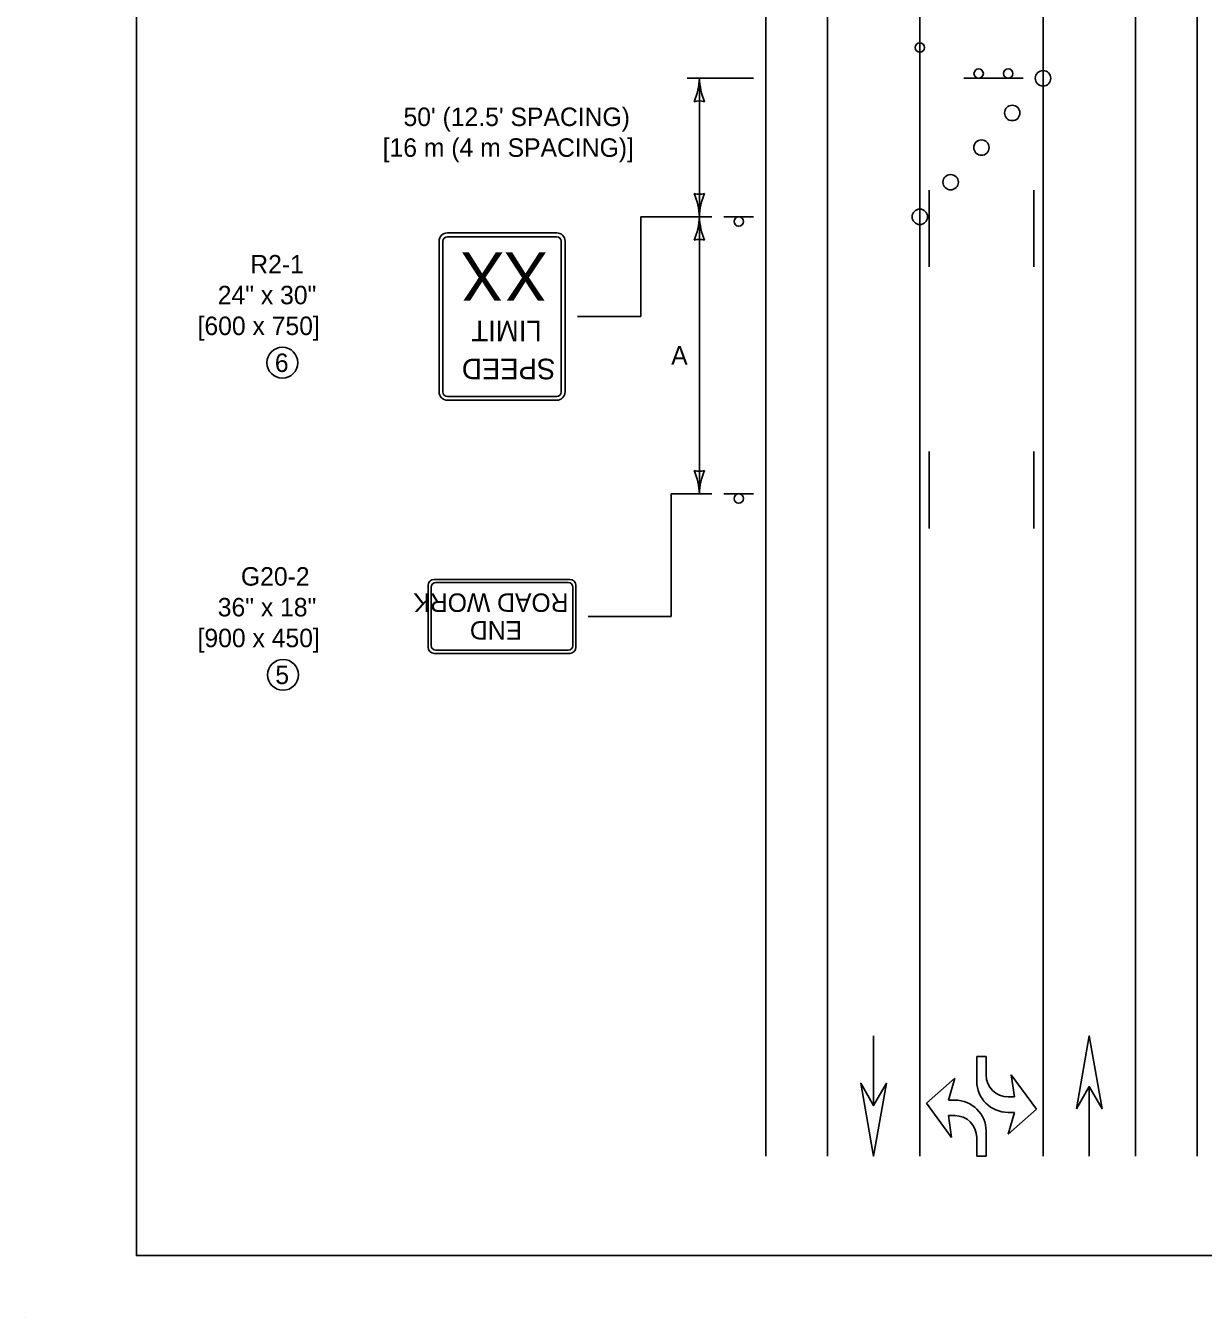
# Model space of a CAD drawing. Extents: x 49991.4 to 50021, y 49987.6 to 50011.4.
# Drawn here: x 49999.977 to 50003.8, y 49999.862 to 50004.057 of the extents above; entities that cross this region are included whole.
import ezdxf

# ---------------------------------------------------------------- set-up
doc = ezdxf.new("R2010")
doc.units = 0
for name, color, linetype in [('Level 1', 7, 'Continuous'), ('Level 2', 7, 'Continuous'), ('Level 3', 7, 'Continuous')]:
    doc.layers.add(name, color=color, linetype=linetype)

msp = doc.modelspace()

# ---------------------------------------------------------------- linework, layer by layer
at = {"layer": 'Level 1'}
for p, q in [((50002.3797, 50000.3857), (50002.3797, 50009.3344)), ((50002.5797, 50000.3857), (50002.5797, 50009.3344)), ((50002.8797, 50000.3857), (50002.8797, 50009.3344)), ((50003.2797, 50000.3857), (50003.2797, 50009.3344)), ((50003.5797, 50000.3857), (50003.5797, 50009.3344)), ((50003.7797, 50000.3857), (50003.7797, 50009.3344)), ((50003.0227, 50003.8868), (50003.1187, 50003.8868)), ((50003.1187, 50003.8868), (50003.2147, 50003.8868)), ((50002.9097, 50003.274), (50002.9097, 50003.524)), ((50003.2497, 50003.274), (50003.2497, 50003.524)), ((50002.2437, 50003.4368), (50002.3397, 50003.4368)), ((50001.3458, 50003.3848), (50001.7004, 50003.3848)), ((50001.3187, 50002.8681), (50001.3187, 50003.3576)), ((50001.3311, 50002.8681), (50001.3311, 50003.3576)), ((50001.3458, 50003.3724), (50001.7004, 50003.3724)), ((50001.7151, 50003.3576), (50001.7151, 50002.8681)), ((50001.7275, 50003.3576), (50001.7275, 50002.8681)), ((50001.7004, 50002.8533), (50001.3458, 50002.8533)), ((50001.7004, 50002.8409), (50001.3458, 50002.8409)), ((50002.9097, 50002.424), (50002.9097, 50002.674)), ((50003.2497, 50002.424), (50003.2497, 50002.674)), ((50002.2437, 50002.5368), (50002.3397, 50002.5368)), ((50001.303, 50002.2589), (50001.743, 50002.2589)), ((50001.2829, 50002.0388), (50001.2829, 50002.2388)), ((50001.2929, 50002.0438), (50001.2929, 50002.2338)), ((50001.3079, 50002.2488), (50001.7379, 50002.2488)), ((50001.7529, 50002.2338), (50001.7529, 50002.0438)), ((50001.7629, 50002.2388), (50001.7629, 50002.0388)), ((50001.3029, 50002.0188), (50001.7429, 50002.0188)), ((50001.3079, 50002.0288), (50001.7379, 50002.0288)), ((50002.7293, 50000.7758), (50002.7293, 50000.5499)), ((50002.7297, 50000.7758), (50002.7297, 50000.5499)), ((50003.095, 50000.7097), (50003.0644, 50000.7097)), ((50003.0644, 50000.7097), (50003.0644, 50000.6289)), ((50003.095, 50000.6491), (50003.095, 50000.7097)), ((50002.9929, 50000.6384), (50002.901, 50000.5576)), ((50002.9725, 50000.5677), (50002.9929, 50000.6384)), ((50003.2583, 50000.5379), (50003.1767, 50000.6491)), ((50003.1767, 50000.6491), (50003.1869, 50000.5783)), ((50003.1604, 50000.5834), (50003.1604, 50000.5834)), ((50003.1869, 50000.5783), (50003.1665, 50000.5783)), ((50003.4297, 50000.3857), (50003.4297, 50000.6116)), ((50003.4299, 50000.3857), (50003.4299, 50000.6116)), ((50002.901, 50000.5576), (50002.9827, 50000.4464)), ((50002.9929, 50000.5677), (50002.9725, 50000.5677)), ((50003.1665, 50000.457), (50003.2583, 50000.5379)), ((50002.9827, 50000.4464), (50002.9725, 50000.5171)), ((50002.9725, 50000.5171), (50002.9929, 50000.5171)), ((50002.999, 50000.5121), (50002.999, 50000.5121)), ((50003.1665, 50000.5278), (50003.1869, 50000.5278)), ((50003.1869, 50000.5278), (50003.1665, 50000.457)), ((50003.0644, 50000.4464), (50003.0644, 50000.3857)), ((50003.095, 50000.3857), (50003.095, 50000.4666)), ((50003.0644, 50000.3857), (50003.095, 50000.3857)), ((49999.9766, 49999.8624), (49999.9766, 49999.8624))]:
    msp.add_line(p, q, dxfattribs=at)
for points in [[(50008.6146, 50011.2628), (50000.3356, 50011.2628), (50000.3356, 50000.0624), (50008.6146, 50000.0624)], [(50003.3879, 50000.5393), (50003.4297, 50000.7758), (50003.4715, 50000.5393), (50003.4297, 50000.6115)], [(50002.7713, 50000.6222), (50002.7297, 50000.3857), (50002.6877, 50000.6222), (50002.7297, 50000.55)]]:
    msp.add_lwpolyline(points, close=True, dxfattribs=at)
for centre, radius in [((50002.8797, 50003.9868), 0.015), ((50003.0707, 50003.902), 0.0152), ((50003.1667, 50003.902), 0.0152), ((50003.2797, 50003.8868), 0.025), ((50003.1797, 50003.7743), 0.025), ((50003.0797, 50003.6618), 0.025), ((50002.9797, 50003.5493), 0.025), ((50002.2917, 50003.4217), 0.0152), ((50002.8797, 50003.4368), 0.025), ((50002.2917, 50002.5217), 0.0152)]:
    msp.add_circle(centre, radius, dxfattribs=at)
for centre, radius, start, end in [((50003.2797, 50003.8868), 0.025, 0, 180), ((50003.2797, 50003.8868), 0.025, 180, 0), ((50003.1797, 50003.7743), 0.025, 0, 180), ((50003.1797, 50003.7743), 0.025, 180, 0), ((50003.0797, 50003.6618), 0.025, 0, 180), ((50003.0797, 50003.6618), 0.025, 180, 0), ((50002.9797, 50003.5493), 0.025, 0, 180), ((50002.9797, 50003.5493), 0.025, 180, 0), ((50002.8797, 50003.4368), 0.025, 0, 180), ((50002.8797, 50003.4368), 0.025, 180, 0), ((50001.3458, 50003.3576), 0.0272, 90, 180), ((50001.7004, 50003.3576), 0.0272, 360, 90), ((50001.3458, 50003.3576), 0.0148, 90, 180), ((50001.7004, 50003.3576), 0.0148, 360, 90), ((50001.3458, 50002.8681), 0.0272, 180, 270), ((50001.3458, 50002.8681), 0.0148, 180, 270), ((50001.7004, 50002.8681), 0.0272, 270, 360), ((50001.7004, 50002.8681), 0.0148, 270, 360), ((50001.303, 50002.2388), 0.02, 90, 180), ((50001.743, 50002.2388), 0.02, 360, 90), ((50001.3079, 50002.2338), 0.015, 90, 180), ((50001.7379, 50002.2338), 0.015, 360, 90), ((50001.3079, 50002.0438), 0.015, 180, 270), ((50001.7379, 50002.0438), 0.015, 270, 360), ((50001.3029, 50002.0388), 0.02, 180, 270), ((50001.7429, 50002.0388), 0.02, 270, 360)]:
    msp.add_arc(centre, radius, start, end, dxfattribs=at)
for centre, major_axis in [((50003.1665, 50000.6289), (-0.1021, 0)), ((50003.1665, 50000.6491), (-0.0715, 0)), ((50002.9929, 50000.4666), (0.1021, 0)), ((50002.9929, 50000.4464), (0.0715, 0))]:
    msp.add_ellipse(centre, major_axis=major_axis, ratio=0.990099, start_param=0, end_param=1.570796, dxfattribs=at)
at = {"layer": 'Level 2'}
for centre in [(50000.8097, 50002.9629), (50000.8117, 50001.9489)]:
    msp.add_circle(centre, 0.0501, dxfattribs=at)
at = {"layer": 'Level 3'}
for p, q in [((50002.1237, 50003.8868), (50002.3397, 50003.8868)), ((50002.1637, 50003.4368), (50002.1637, 50003.8868)), ((50001.9734, 50003.4368), (50002.2037, 50003.4368)), ((50002.1637, 50002.5368), (50002.1637, 50003.4368)), ((50001.7675, 50003.1128), (50001.9734, 50003.1128)), ((50002.2037, 50002.5368), (50002.0718, 50002.5368))]:
    msp.add_line(p, q, dxfattribs=at)
for points in [[(50001.9734, 50003.1128), (50001.9734, 50003.4368)], [(50001.8029, 50002.1388), (50002.0718, 50002.1388), (50002.0718, 50002.5368)]]:
    msp.add_lwpolyline(points, dxfattribs=at)
for centre, radius, start, end in [((50001.9416, 50003.896), 0.2223, 337.456, 357.6395), ((50002.3964, 50003.8983), 0.233, 182.8273, 202.0772), ((50002.1637, 50003.7586), 0.0548, 72.1388, 107.8612), ((50002.1637, 50003.5651), 0.0548, 252.1388, 287.8612), ((50001.931, 50003.4253), 0.233, 2.8273, 22.0772), ((50002.3858, 50003.4277), 0.2223, 157.456, 177.6395), ((50001.9416, 50003.446), 0.2223, 337.456, 357.6395), ((50002.3964, 50003.4483), 0.233, 182.8273, 202.0772), ((50002.1637, 50003.3086), 0.0548, 72.1388, 107.8612), ((50002.1637, 50002.6651), 0.0548, 252.1388, 287.8612), ((50001.931, 50002.5253), 0.233, 2.8273, 22.0772), ((50002.3858, 50002.5277), 0.2223, 157.456, 177.6395)]:
    msp.add_arc(centre, radius, start, end, dxfattribs=at)

# ---------------------------------------------------------------- texts
at = {"layer": 'Level 1'}
for s, height, p in [('XX', 0.15775, (50001.6702, 50003.3218)), ('LIMIT', 0.06696, (50001.6519, 50003.0998)), ('SPEED', 0.06696, (50001.6962, 50002.976)), ('ROAD WORK', 0.06, (50001.7388, 50002.2135)), ('END', 0.06, (50001.5881, 50002.1235))]:
    msp.add_text(s, height=height, rotation=180, dxfattribs=at).set_placement(p)
at = {"layer": 'Level 2'}
for s, p in [("50' (12.5' SPACING)", (50001.203, 50003.7318)), ('[16 m (4 m SPACING)]', (50001.1353, 50003.6318)), ('R2-1', (50000.7053, 50003.2528)), ('24" x 30"', (50000.5998, 50003.1528)), ('[600 x 750]', (50000.5342, 50003.0528)), ('6', (50000.7852, 50002.9329)), ('G20-2', (50000.675, 50002.2388)), ('36" x 18"', (50000.5998, 50002.1388)), ('[900 x 450]', (50000.5342, 50002.0388)), ('5', (50000.7868, 50001.9189))]:
    msp.add_text(s, height=0.06, dxfattribs=at).set_placement(p)
msp.add_text('A', height=0.06, rotation=360, dxfattribs=at).set_placement((50002.0722, 50002.9568))

doc.saveas('drawing.dxf')
